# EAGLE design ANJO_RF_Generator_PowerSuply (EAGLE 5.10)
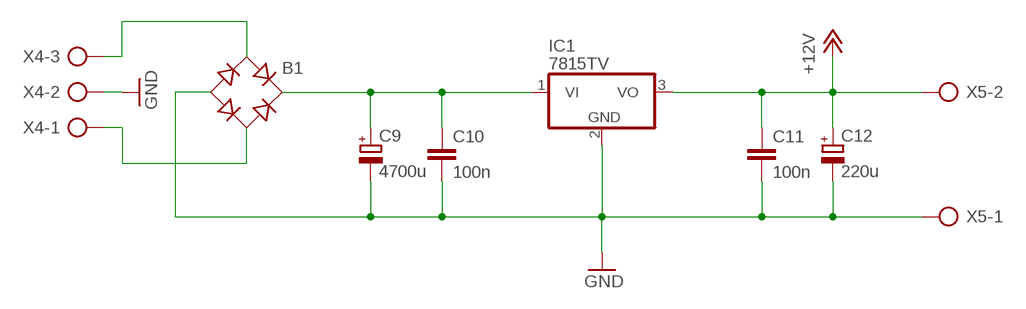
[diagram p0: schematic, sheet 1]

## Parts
B1  RB1A  [RB1A]
C9  4700u  CPOL-EUE10-22.5  [EB22,5D]
C10  100n  C-EU075-032X103  [C075-032X103]
C11  100n  C-EU075-032X103  [C075-032X103]
C12  220u  CPOL-EUE5-8.5  [E5-8,5]
IC1  7815TV  [TO220V]
X4  AK300/3  [AK300/3]
X5  AK300/2  [AK300/2]

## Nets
+12V: C11.1 C12.+ IC1.3(VO) X5.2
GND: B1.- C9.- C10.2 C11.2 C12.- IC1.2(GND) X4.2 X5.1
N$36: B1.+ C9.+ C10.1 IC1.1(VI)
N$41: B1.AC2 X4.1
N$43: B1.AC1 X4.3

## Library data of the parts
B1 = rectifier:RB1A: RECTIFIER 1 A
C9 C12 = resistor:CPOL-EU: POLARIZED CAPACITOR, European symbol
C10 C11 = resistor:C-EU: CAPACITOR, European symbol
IC1 = linear:78*: Positive VOLTAGE REGULATOR Source: http://cache.national.com/ds/LM/LM78L05.pdf http://www.fairchildsemi.com/ds/LM/LM7805.pdf
X4 = con-ptr500:AK300/3: CONNECTOR
X5 = con-ptr500:AK300/2: CONNECTOR

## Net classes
0 default: width 0.559 mm, drill 0.559 mm, clearance 0.559 mm

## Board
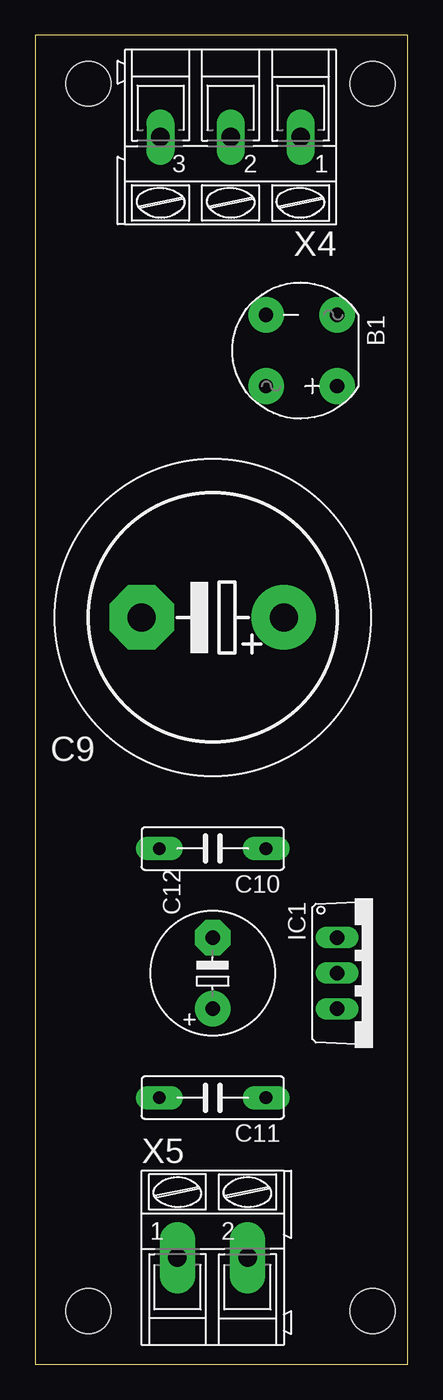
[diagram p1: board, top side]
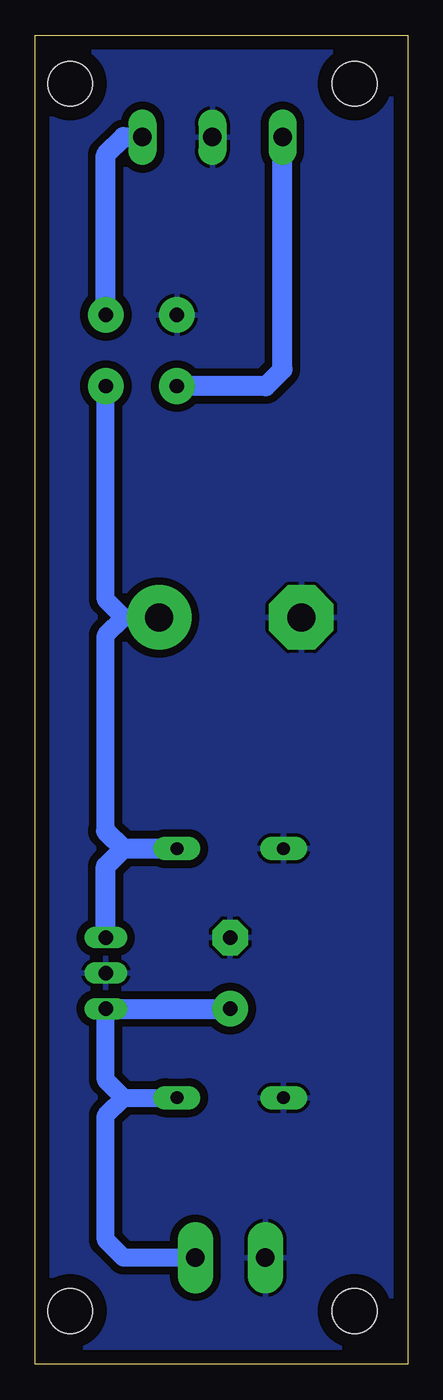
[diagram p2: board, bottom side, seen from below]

Size 26.65 x 94.92 mm. Coordinates in mm from the lower left corner, seen from the top.
Outline: 0,0 26.65,0 26.65,94.92 0,94.92 0,0
Copper layers (1*16): Top 0.035mm / dielectric 1.5mm / Bottom 0.035mm
Design rules "default": minimum track width 10mil, minimum drill 24mil, track to track 8mil, track to pad 8mil, pad to pad 8mil, via to via 8mil, smd to smd 8mil, copper to edge 40mil, drill to drill 8mil, minimum pad ring 10mil, minimum via ring 8mil, stop-mask expansion 4mil, vias tented up to drill 0mil, thermal gap 10mil
Holes 3.2 mm at 3.81,91.44 24.13,91.44 24.13,3.81 3.81,3.81

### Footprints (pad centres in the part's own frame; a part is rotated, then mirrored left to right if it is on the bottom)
RB1A = drill 1.016 pad 2.54 round: + -2.54,2.54; - 2.54,-2.54; AC1 2.54,2.54; AC2 -2.54,-2.54
EB22,5D = drill 2.007 pad 4.597 round: + -5.08,0 | drill 2.007 pad 4.597 octagon: - 5.08,0
C075-032X103 = drill 0.914 pad 1.676 long: 1 -3.81,0; 2 3.81,0
E5-8,5 = drill 1.016 pad 2.54 round: + -2.54,0 | drill 1.016 pad 2.54 octagon: - 2.54,0
TO220V = drill 1.016 long: 1 -2.54,-2.54; 2 0,-2.54; 3 2.54,-2.54
AK300/3 = drill 1.321 long: 1 -5.004,0; 2 0,0; 3 5.004,0
AK300/2 = drill 1.321 pad 2.54 long: 1 -2.515,0; 2 2.489,0

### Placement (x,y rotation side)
B1  19.05,72.39 180 top
C9  12.7,53.34 180 top
C10  12.7,36.83 180 top
C11  12.7,19.05 180 top
C12  12.7,27.94 90 top
IC1  24.13,27.94 270 top
X4  13.97,87.63 180 top
X5  12.7,7.62 0 top

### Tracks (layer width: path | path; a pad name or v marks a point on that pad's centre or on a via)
+12V
  Bottom 1.27: X5.2 20.32,7.62 21.59,8.89 21.59,17.78 20.32,19.05 | 20.32,19.05 C11.1 | 20.32,19.05 21.59,20.32 IC1.3
  Bottom 1.422: IC1.3 C12.+
GND
  pour Bottom: -1.27,96.52 27.94,96.52 27.94,-1.27 -1.27,-1.27
N$36
  Bottom 1.27: 21.59,38.1 21.59,52.07 20.32,53.34 | 20.32,53.34 C9.+ | 20.32,53.34 21.59,54.61 B1.+
  Bottom 1.422: 20.32,36.83 21.59,38.1 | 20.32,36.83 C10.1 | 20.32,36.83 21.59,35.56 IC1.1
N$41
  Bottom 1.422: X4.1 20.32,87.63 21.59,86.36 B1.AC2
N$43
  Bottom 1.422: X4.3 8.97,71.04 10.16,69.85 B1.AC1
